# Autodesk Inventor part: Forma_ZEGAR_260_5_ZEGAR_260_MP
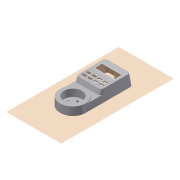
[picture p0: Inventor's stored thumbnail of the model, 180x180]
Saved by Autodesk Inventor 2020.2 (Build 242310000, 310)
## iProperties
Created: 2015-01
Part Number: Forma_ZEGAR_260_5_ZEGAR_260_MP
Material: Ogólny
Document SubType Name: Modeling
Designer: F.Stasiak
Density: 1 g/cm^3
Appearance: Domyślna
Catalog Web Link: www.expertbooks.pl
Manager: www.cadconsulting.pl
Company: Fabian Stasiak CAD Consulting
Author: F.Stasiak
Subject: Zbiór ćwiczeń. Autodesk Inventor 2020. Kurs Professional
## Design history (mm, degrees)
derived "ZEGAR_260.ipt"
node "Forma_ZEGAR_260_4_ZEGAR_260_WP"
feature "Zamknij obwiednię1" dims "d7" = 5, "d8" = 5, "d9" = 5, "d10" = 5, "d11" = 0
feature "Zamknij obwiednię2" dims "d12" = 5, "d13" = 5, "d14" = 5, "d15" = 5, "d16" = 0
feature "Zamknij obwiednię3" dims "d17" = 5, "d18" = 5, "d19" = 5, "d20" = 5, "d21" = 5, "d22" = 5, "d23" = 5, "d24" = 5, "d25" = 0
feature "Zamknij obwiednię4" dims "d26" = 5, "d27" = 5, "d28" = 5, "d29" = 5, "d30" = 0
feature "Zamknij obwiednię5" dims "d31" = 5, "d32" = 5, "d33" = 5, "d34" = 5, "d35" = 0
feature "Zamknij obwiednię6" dims "d36" = 5, "d37" = 5, "d38" = 5, "d39" = 5, "d40" = 0
feature "Zamknij obwiednię7" dims "d41" = 5, "d42" = 5, "d43" = 5, "d44" = 5, "d45" = 0
feature "Zamknij obwiednię8" dims "d46" = 5, "d47" = 5, "d48" = 5, "d49" = 5, "d50" = 0
feature "Zamknij obwiednię9" dims "d51" = 5, "d52" = 5, "d53" = 5, "d54" = 5, "d55" = 0
feature "Zamknij obwiednię10" dims "d56" = 5, "d57" = 0
feature "Zamknij obwiednię11" dims "d58" = 5, "d59" = 0
feature "Zamknij obwiednię12" dims "d60" = 5, "d61" = 0
node "Płaszczyzna konstrukcyjna1"
sketch "Szkic1"
  geometry: L1 (30.835, -178.031)-(30.835, 61.969); L2 (30.835, 61.969)-(-86.165, 61.969); L3 (-86.165, 61.969)-(-86.165, -178.031); L4 (-86.165, -178.031)-(30.835, -178.031); L5 (0, 0)-(0, -94.499) reference; L6 (-55.33, -94.499)-(-55.33, 0) reference; L7 (-49.319, 6.101)-(-6.011, 6.101) reference; A1 r 27.665 centre (-27.665, -94.499) between (-55.33, -94.499) and (0, -94.499) reference; 3 further points; 2 other entities
  constraints: 8 end point, 2 other
  dimensions: "d62" = 58.5 horizontal distance of point (-27.665, -58.031) L1.end (= 1.5 x Xmax); "d63" = 120 vertical distance of point (-27.665, -58.031) L1.end (= 1.5 x Ymax); "d64" = 58.5 horizontal distance of point (-27.665, -58.031) L2.end (= -1.5 x Xmin); "d65" = 120 vertical distance of point (-27.665, -58.031) L2.end (= 1.5 x Ymax); "d66" = 58.5 horizontal distance of point (-27.665, -58.031) L3.end (= -1.5 x Xmin); "d67" = 120 vertical distance of point (-27.665, -58.031) L3.end (= -1.5 x Ymin); "d68" = 58.5 horizontal distance of point (-27.665, -58.031) L1.start (= 1.5 x Xmax); "d69" = 120 vertical distance of point (-27.665, -58.031) L1.start (= -1.5 x Ymin)
feature "Zamknij obwiednię13" sketch "Szkic1"
feature "Oddzielenie matrycy1"
node "Płaszczyzna konstrukcyjna2"
sketch "Szkic2"
  geometry: L1 (0, -78)-(-20.191, -78) reference; L2 (-20.191, -78)-(-20.191, 0) reference; L3 (-17.791, -39)-(-12.991, -39); L4 (-17.791, -39)-(-15.391, -39); L5 (-17.791, -39)-(-17.791, -29.75); L6 (-20.191, -48.25)-(-15.391, -48.25); L7 (-15.391, -48.25)-(-15.391, -29.75); L8 (-15.391, -29.75)-(-20.191, -29.75); L9 (-20.191, -29.75)-(-20.191, -48.25)
  constraints: 14 end point, 1 horizontal, 1 perpendicular, 2 other
  dimensions: "d71" = 39 distance from line of L1 L3.start; "d72" = 2.4 distance from line of L2 L3.start; "d73" = 0 distance between parallel lines of L3 L4; "d74" = 4.8 distance between parallel lines of L9 L7; "d75" = 18.5 distance between parallel lines of L8 L6
extrude "Wyciągnięcie proste1" new body sketch "Szkic2" stored distance "d76" = 0.13; taper "d77" = 0 deg
node "Płaszczyzna konstrukcyjna3"
sketch "Szkic3"
  geometry: L1 (0, -18.5)-(-4.8, -18.5) reference; L2 (-4.8, -18.5)-(-4.8, 0) reference; L3 (-1.8, -9.25)-(4.2, -9.25); L4 (-1.8, -9.25)-(1.2, -9.25); L5 (-1.8, -9.25)-(-1.8, 5.75); L6 (-4.8, -24.25)-(1.2, -24.25); L7 (1.2, -24.25)-(1.2, 5.75); L8 (1.2, 5.75)-(-4.8, 5.75); L9 (-4.8, 5.75)-(-4.8, -24.25)
  constraints: 14 end point, 1 horizontal, 1 perpendicular, 2 other
  dimensions: "d79" = 9.25 distance from line of L1 L3.start; "d80" = 3 distance from line of L2 L3.start; "d81" = 0 distance between parallel lines of L3 L4; "d82" = 6 distance between parallel lines of L9 L7; "d83" = 30 distance between parallel lines of L8 L6
extrude "Wyciągnięcie proste2" join sketch "Szkic3" distance "d84" = 8; taper "d85" = 0 deg
feature "Bryła1::ZEGAR_260.ipt"
tag "Bryła wyprowadzona1"
feature "Bryła1::Forma_ZEGAR_260_4_ZEGAR_260_WP"
tag "Bryła wyprowadzona2"
body "Srf1"
body "Srf2"
body "Srf3"
body "Srf4"
body "Srf5"
body "Srf6"
body "Srf7"
body "Srf8"
body "Srf9"
body "Srf10"
body "Srf11"
body "Srf12"
body "Srf13"
node "Bryła3"
node "Bryła4"
node "Bryła5"
node "Bryła1"
feature "ZEGAR_260.ipt_Bodies"
node "Bryła2"
feature "Forma_ZEGAR_260_4_ZEGAR_260_WP_Bodies"
other parameters: "d1" = 39, "d2" = 39, "d6" = 0, "Xmin" = -39, "Xmax" = 39, "d70" = 0, "d78" = 0
